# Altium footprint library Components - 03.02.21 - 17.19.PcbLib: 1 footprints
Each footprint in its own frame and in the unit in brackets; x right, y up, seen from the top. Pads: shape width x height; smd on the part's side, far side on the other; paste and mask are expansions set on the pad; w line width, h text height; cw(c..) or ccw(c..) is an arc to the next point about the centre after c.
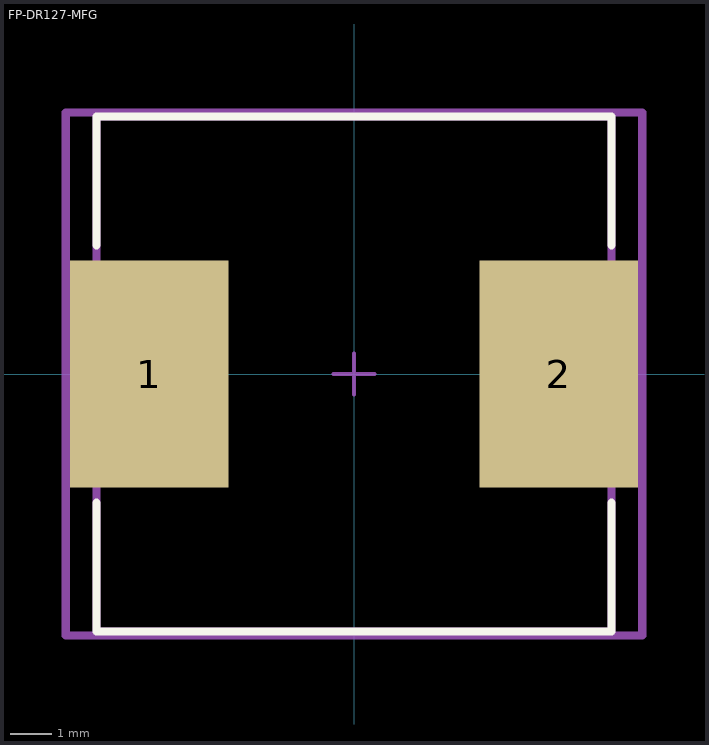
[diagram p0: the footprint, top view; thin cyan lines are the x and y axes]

## FP-DR127-MFG [mm]
pads (2):
  rect 3.85x5.5 smd paste+0 mask+0: 1(-4.975,0) 2(4.975,0)
Top Overlay:
  lines w0.2: -6.25,-3.125 -6.25,-6.25 6.25,-6.25 6.25,-3.125 ; -6.25,3.125 -6.25,6.25 6.25,6.25 6.25,3.125
Mechanical 5:
  lines w0.2: -7,-6.35 7,-6.35 7,6.35 -7,6.35 -7,-6.35
  text ".Designator" at 0,0.188 h1
Mechanical 13:
  lines w0.2: -6.25,-6.25 6.25,-6.25 6.25,6.25 -6.25,6.25 -6.25,-6.25
Mechanical 15:
  lines w0.2: -7,-6.35 7,-6.35 7,6.35 -7,6.35 -7,-6.35
Mechanical 16:
  lines w0.1: -0.5,0 0.5,0 ; 0,-0.5 0,0.5
3D body "Ind_Eaton_DR127-470-R_eec.STEP": height 0.25, standoff 0, extent -7,-6.35 7,6.35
